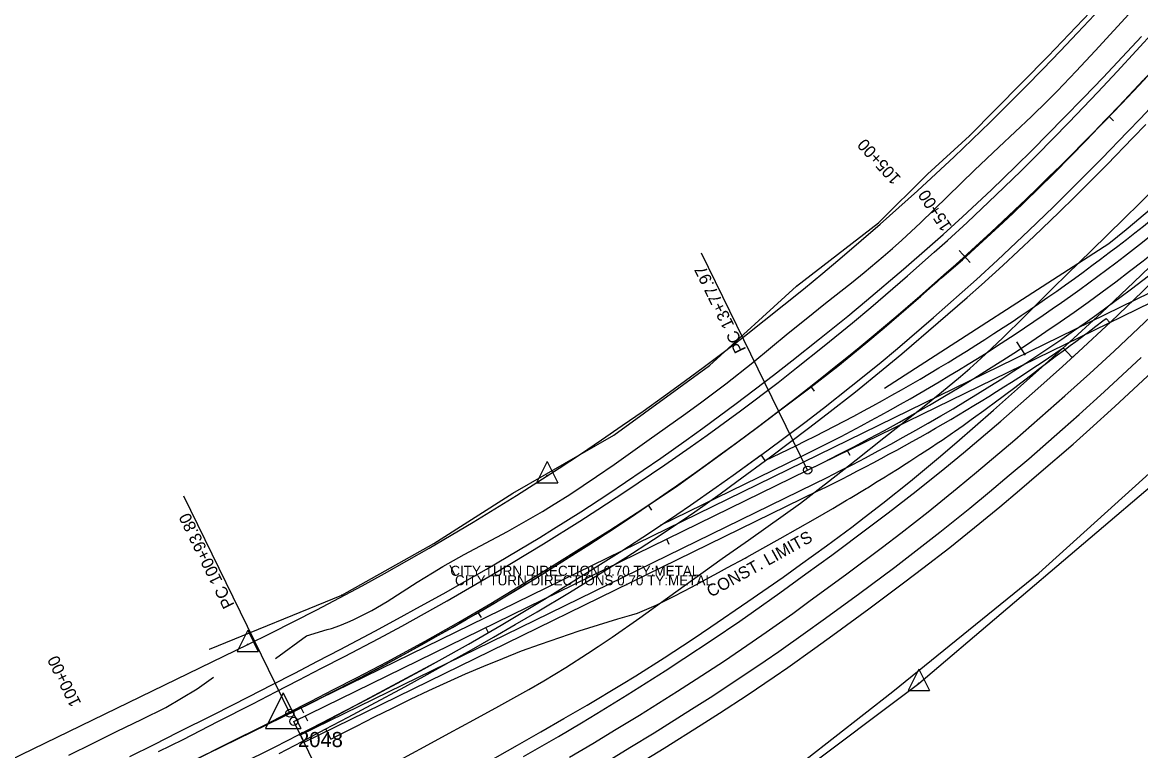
# Model space of a CAD drawing. Extents: x 1674300 to 1677920, y 225056 to 231852.
# Drawn here: x 1676432 to 1676987, y 227668 to 228030 of the extents above; entities that cross this region are included whole.
import ezdxf

# ---------------------------------------------------------------- set-up
doc = ezdxf.new("R2010")
doc.units = 0
for name, color, linetype in [('R_Annotation', 7, 'Continuous'), ('R_Horz Alg', 7, 'Continuous'), ('R_Horz Alg Annot', 7, 'Continuous'), ('R_Proposed Const Limits_Fill', 7, 'Continuous'), ('R_Proposed Road_Lane', 7, 'Continuous'), ('R_Proposed Road_Shoulder', 7, 'Continuous'), ('S_CAL_CORNER', 7, 'Continuous'), ('S_CAL_CORNER_ANNOT', 7, 'Continuous'), ('S_DITCHLINE', 7, 'Continuous'), ('S_EDGE_PAVEMENT', 7, 'Continuous'), ('S_EXIST_ROW', 7, 'Continuous'), ('S_EXISTING_ALIGNMENT', 7, 'Continuous'), ('S_FIBER_OPTIC_CABLE', 7, 'Continuous'), ('S_MSC_PT_SYM', 7, 'Continuous'), ('S_PAVEMENT_CROWN', 7, 'Continuous'), ('S_SHOULDER', 7, 'Continuous'), ('S_SIGN', 7, 'Continuous'), ('S_SIGN_ANNOT', 7, 'Continuous'), ('S_UTL_PT_SYM', 7, 'Continuous')]:
    doc.layers.add(name, color=color, linetype=linetype)

msp = doc.modelspace()

# ---------------------------------------------------------------- linework, layer by layer
at = {"layer": 'R_Horz Alg'}
for p, q in [((1676566.75, 227682.84), (1676822.03, 227807.69)), ((1676115.61, 227467.2), (1676564.78, 227686.88))]:
    msp.add_line(p, q, dxfattribs=at)
for centre, radius, end in [((1675928.16, 228988.54), 1449, 0.80558), ((1676402.48, 228665.51), 954.93, 328.88259)]:
    msp.add_arc(centre, radius, 296.0624, end, dxfattribs=at)
at = {"layer": 'R_Horz Alg Annot'}
for p, q in [((1676564.78, 227686.88), (1677389.93, 228090.45)), ((1676822.03, 227807.69), (1677074.66, 227931.25))]:
    msp.add_line(p, q, dxfattribs=at)
for points in [[(1676974.02, 227981.32), (1676971.86, 227983.41)], [(1676822.03, 227807.69), (1676769.3, 227915.48)], [(1676897.38, 227916.79), (1676902.74, 227910.86)], [(1676925.73, 227871.49), (1676930.13, 227864.81)], [(1676825.49, 227847.01), (1676823.64, 227849.36)], [(1676843.08, 227814.93), (1676841.7, 227817.59)], [(1676564.78, 227686.88), (1676512.05, 227794.68)], [(1676744.64, 227787.84), (1676742.95, 227790.32)], [(1676753.3, 227770.74), (1676751.99, 227773.43)], [(1676659.89, 227734.4), (1676658.38, 227736.99)], [(1676663.47, 227726.8), (1676662.15, 227729.5)], [(1676571.67, 227686.93), (1676570.34, 227689.61)], [(1676619.47, 227575.04), (1676566.75, 227682.84)], [(1676573.64, 227682.87), (1676572.32, 227685.56)]]:
    msp.add_lwpolyline(points, dxfattribs=at)
for centre in [(1676822.03, 227807.69), (1676564.78, 227686.88), (1676566.75, 227682.84)]:
    msp.add_circle(centre, 2, dxfattribs=at)
at = {"layer": 'R_Proposed Const Limits_Fill'}
for p, q in [((1676970.31, 227883.06), (1676972.23, 227881.05)), ((1676585.15, 227673.94), (1676582.55, 227679.05))]:
    msp.add_line(p, q, dxfattribs=at)
for points in [[(1676860.25, 227848.42), (1676971.76, 227920.24)], [(1676585.15, 227673.94), (1676588.94, 227675.93), (1676597.88, 227680.41), (1676606.76, 227685.02), (1676615.73, 227689.44), (1676624.67, 227693.92), (1676633.73, 227698.17), (1676642.85, 227702.29), (1676651.99, 227706.38), (1676661.2, 227710.33), (1676670.5, 227714.1), (1676679.82, 227717.84), (1676689.32, 227721.21), (1676698.84, 227724.53), (1676708.42, 227727.76), (1676718.1, 227730.78), (1676727.79, 227733.78), (1676734.61, 227735.81), (1676737.54, 227736.67), (1676746.79, 227740.54), (1676755.71, 227745.06), (1676764.59, 227749.65), (1676773.38, 227754.43), (1676777.77, 227756.83), (1676782.16, 227759.23), (1676790.94, 227764.02), (1676791.82, 227764.49), (1676799.7, 227768.86), (1676808.45, 227773.71), (1676817.16, 227778.65), (1676825.85, 227783.62), (1676834.5, 227788.69), (1676841.39, 227792.77), (1676843.11, 227793.8), (1676851.16, 227798.64), (1676851.72, 227798.97), (1676856.62, 227801.97), (1676860.5, 227804.37), (1676862.05, 227805.32), (1676867.46, 227808.7), (1676869.23, 227809.82), (1676872.83, 227812.15), (1676877.85, 227815.42), (1676878.17, 227815.64), (1676883.52, 227819.1), (1676886.46, 227821.03), (1676888.82, 227822.64), (1676894.08, 227826.23), (1676894.95, 227826.82), (1676899.3, 227829.88), (1676903.32, 227832.77), (1676904.47, 227833.6), (1676909.62, 227837.34), (1676911.62, 227838.8), (1676914.76, 227841.08), (1676919.83, 227844.91), (1676919.84, 227844.92), (1676924.9, 227848.75), (1676928.01, 227851.1), (1676929.95, 227852.58), (1676934.98, 227856.45), (1676936.12, 227857.33), (1676939.99, 227860.33), (1676944.26, 227863.49), (1676945.07, 227864.09), (1676950.14, 227867.87), (1676952.43, 227869.57), (1676955.21, 227871.64), (1676960.26, 227875.42), (1676960.59, 227875.66), (1676965.3, 227879.22), (1676968.69, 227881.82), (1676970.31, 227883.06)]]:
    msp.add_lwpolyline(points, dxfattribs=at)
msp.add_arc((1676364.65, 228668.23), 963.36, 309.06481, 319.55161, dxfattribs=at)
at = {"layer": 'R_Proposed Road_Lane'}
for p, q in [((1676748.93, 227780.28), (1676818.73, 227814.42)), ((1676570.05, 227676.1), (1676825.32, 227800.95)), ((1676570.05, 227676.1), (1676638.9, 227713))]:
    msp.add_line(p, q, dxfattribs=at)
for points in [[(1676953.5, 227863.64), (1676956.64, 227866.52), (1676972.6, 227881.4), (1676988.37, 227896.5), (1676996.17, 227904.12), (1677007.75, 227915.68), (1677022.13, 227930.45), (1677031.62, 227940.39), (1677041.04, 227950.41), (1677050.47, 227960.42), (1677064.47, 227975.57), (1677071.28, 227983.29), (1677077.87, 227991.2), (1677081.05, 227995.24), (1677086, 228001.89), (1677089.18, 228006.41), (1677095.28, 228015.66), (1677102.54, 228027.13)], [(1676602.96, 227693.74), (1676603.67, 227694.11), (1676620.43, 227702.92), (1676631.53, 227708.93), (1676638.9, 227713), (1676653.56, 227721.26), (1676669.8, 227730.7), (1676680.55, 227737.1), (1676691.25, 227743.62), (1676701.94, 227750.13), (1676720.46, 227761.74), (1676729.67, 227767.63), (1676743.4, 227776.59), (1676757.03, 227785.7), (1676763.8, 227790.32), (1676776.54, 227799.18), (1676784.98, 227805.17), (1676798.91, 227815.26)]]:
    msp.add_lwpolyline(points, dxfattribs=at)
for radius, end in [(947.43, 317.63818), (962.43, 309.63823)]:
    msp.add_arc((1676402.48, 228665.51), radius, 296.0624, end, dxfattribs=at)
at = {"layer": 'R_Proposed Road_Shoulder'}
for p, q in [((1676949.06, 227868.5), (1676953.5, 227863.64)), ((1676800.97, 227812.42), (1676798.91, 227815.26)), ((1676800.97, 227812.42), (1676816.09, 227819.81)), ((1676571.81, 227672.51), (1676827.08, 227797.35)), ((1676571.81, 227672.51), (1676569.81, 227676.59))]:
    msp.add_line(p, q, dxfattribs=at)
for radius, end in [(941.43, 317.05629), (966.43, 304.44158)]:
    msp.add_arc((1676402.48, 228665.51), radius, 296.0624, end, dxfattribs=at)
at = {"layer": 'S_CAL_CORNER'}
for p, q in [((1676561.42, 227697.02), (1676552.61, 227679.29)), ((1676561.42, 227697.02), (1676552.61, 227679.29)), ((1676561.42, 227697.02), (1676552.61, 227679.29)), ((1676561.42, 227697.02), (1676552.61, 227679.29)), ((1676561.42, 227697.02), (1676570.14, 227679.29)), ((1676561.42, 227697.02), (1676570.14, 227679.29)), ((1676561.42, 227697.02), (1676570.14, 227679.29)), ((1676561.42, 227697.02), (1676570.14, 227679.29)), ((1676552.61, 227679.29), (1676570.14, 227679.29)), ((1676552.61, 227679.29), (1676570.14, 227679.29)), ((1676552.61, 227679.29), (1676570.14, 227679.29)), ((1676552.61, 227679.29), (1676570.14, 227679.29))]:
    msp.add_line(p, q, dxfattribs=at)
at = {"layer": 'S_DITCHLINE'}
for points in [[(1676557.64, 227714.12), (1676573.09, 227725.4), (1676583.33, 227728.42), (1676585.43, 227729.06), (1676589.57, 227730.51), (1676593.62, 227732.15), (1676596.28, 227733.34), (1676601.53, 227735.92), (1676605.4, 227738), (1676613.02, 227742.46), (1676628.03, 227751.95), (1676635.56, 227756.66), (1676640.82, 227759.78), (1676651.43, 227765.74), (1676672.81, 227777.22), (1676683.4, 227783.11), (1676690.27, 227787.16), (1676694.8, 227789.93), (1676703.79, 227795.62), (1676717.1, 227804.49), (1676725.88, 227810.55), (1676743.33, 227822.85), (1676760.37, 227834.97), (1676768.81, 227841.12), (1676781.31, 227850.55), (1676794.72, 227861.22), (1676812.4, 227875.73), (1676821.28, 227882.95), (1676830.91, 227890.62), (1676843.77, 227900.81), (1676850.15, 227905.95), (1676859.6, 227913.82), (1676864.24, 227917.84), (1676868.89, 227922.01), (1676878.02, 227930.53), (1676891.46, 227943.62), (1676904.91, 227956.71), (1676917.04, 227968.18), (1676933.22, 227983.46), (1676941.18, 227991.22), (1676946.01, 227996.08), (1676955.51, 228005.96), (1676964.85, 228016), (1676974.11, 228026.12), (1676983.36, 228036.25)], [(1676619.21, 227663.52), (1676631.55, 227670.24), (1676643.88, 227676.95), (1676656.22, 227683.66), (1676668.56, 227690.37), (1676683.49, 227698.72), (1676690.87, 227703.03), (1676701.83, 227709.66), (1676712.65, 227716.51), (1676718, 227720.02), (1676724.96, 227724.71), (1676738.72, 227734.32), (1676752.33, 227744.15), (1676765.94, 227753.99), (1676779.59, 227763.79), (1676792.57, 227772.92), (1676809.85, 227785.11), (1676818.4, 227791.33), (1676832.36, 227801.97), (1676846.14, 227812.86), (1676859.92, 227823.76), (1676879.09, 227838.84), (1676888.6, 227846.47), (1676897.95, 227854.27), (1676902.55, 227858.26), (1676908.13, 227863.25), (1676919.05, 227873.5), (1676929.77, 227883.98), (1676943.92, 227898.11), (1676951.02, 227905.16), (1676963.08, 227916.92), (1676979.21, 227932.56), (1676987.2, 227940.45), (1677000.17, 227953.65)], [(1676454.95, 227666.05), (1676466.98, 227671.97), (1676479.02, 227677.89), (1676491.05, 227683.81), (1676503.09, 227689.73), (1676518.65, 227699.02), (1676526.82, 227704.87)]]:
    msp.add_lwpolyline(points, dxfattribs=at)
at = {"layer": 'S_EDGE_PAVEMENT'}
for points in [[(1676499.45, 227667.86), (1676511.68, 227673.86), (1676528.99, 227682.71), (1676546.31, 227691.55), (1676557.7, 227697.44), (1676569.08, 227703.32), (1676580.47, 227709.21), (1676591.86, 227715.09), (1676608.97, 227724.09), (1676620.31, 227730.21), (1676631.57, 227736.48), (1676642.83, 227742.74), (1676664.28, 227755.12), (1676674.93, 227761.44), (1676690.82, 227771.09), (1676708.87, 227782.39), (1676717.84, 227788.15), (1676731.2, 227796.91), (1676751.05, 227810.35), (1676763.67, 227819.17), (1676772.03, 227825.14), (1676788.62, 227837.24), (1676807.31, 227851.32), (1676816.56, 227858.49), (1676830.31, 227869.4), (1676844.24, 227880.82), (1676853.44, 227888.54), (1676871.63, 227904.22), (1676884.89, 227915.95), (1676891.46, 227921.87), (1676901.25, 227930.84), (1676915.74, 227944.48), (1676927.9, 227956.29), (1676935.92, 227964.26), (1676951.76, 227980.38), (1676966.27, 227995.53), (1676975.83, 228005.73), (1676985.29, 228016.04), (1676994.74, 228026.34)], [(1676539.8, 227661.38), (1676557.45, 227670.2), (1676569.01, 227676.18), (1676580.56, 227682.15), (1676592.12, 227688.13), (1676603.67, 227694.11), (1676620.43, 227702.92), (1676631.53, 227708.93), (1676638.9, 227713), (1676653.56, 227721.26), (1676669.8, 227730.7), (1676680.55, 227737.1), (1676691.25, 227743.62), (1676701.94, 227750.13), (1676720.46, 227761.74), (1676729.67, 227767.63), (1676743.4, 227776.59), (1676757.03, 227785.7), (1676763.8, 227790.32), (1676776.54, 227799.18), (1676784.98, 227805.17), (1676801.74, 227817.32), (1676820.56, 227831.36), (1676829.88, 227838.49), (1676843.73, 227849.37), (1676857.53, 227860.58), (1676866.63, 227868.17), (1676884.63, 227883.6), (1676898.83, 227896.15), (1676905.87, 227902.49), (1676916.35, 227912.09), (1676931.88, 227926.7), (1676944.11, 227938.52), (1676952.18, 227946.48), (1676968.16, 227962.57), (1676980.99, 227975.79), (1676987.34, 227982.45), (1676996.8, 227992.52)], [(1676680.84, 227665.29), (1676698.16, 227675.29), (1676709.63, 227682.09), (1676717.25, 227686.68), (1676732.39, 227696.01), (1676751.22, 227707.95), (1676760.57, 227714.03), (1676774.51, 227723.28), (1676788.32, 227732.7), (1676795.19, 227737.48), (1676808.2, 227746.7), (1676821.09, 227756.09), (1676833.98, 227765.47), (1676852.77, 227779.44), (1676862.1, 227786.51), (1676875.97, 227797.27), (1676890.15, 227808.64), (1676899.5, 227816.34), (1676917.98, 227832.01), (1676936.44, 227848.2), (1676948.6, 227859.15), (1676956.64, 227866.52), (1676972.6, 227881.4), (1676988.37, 227896.5)], [(1676721.65, 227662.42), (1676733.68, 227669.77), (1676745.7, 227677.12), (1676764.28, 227688.81), (1676773.52, 227694.75), (1676787.29, 227703.77), (1676800.96, 227712.96), (1676807.74, 227717.62), (1676821.02, 227726.94), (1676829.81, 227733.24), (1676847.27, 227746), (1676865.35, 227759.54), (1676874.33, 227766.39), (1676887.68, 227776.81), (1676902.58, 227788.79), (1676912.41, 227796.9), (1676922.15, 227805.14), (1676931.88, 227813.37), (1676948.66, 227827.99), (1676956.98, 227835.38), (1676969.35, 227846.58), (1676978.52, 227855.1), (1676987.68, 227863.63)]]:
    msp.add_lwpolyline(points, dxfattribs=at)
at = {"layer": 'S_EXIST_ROW'}
for p, q in [((1676877.29, 227701.73), (1677045.25, 227844.61)), ((1676692.64, 227812.02), (1676687.35, 227801.39)), ((1676692.64, 227812.02), (1676697.88, 227801.39)), ((1676692.62, 227804.93), (1676692.62, 227804.93)), ((1676687.35, 227801.39), (1676697.88, 227801.39)), ((1676543.81, 227728.11), (1676538.52, 227717.47)), ((1676543.81, 227728.11), (1676549.04, 227717.47)), ((1676060.31, 227485.79), (1676543.79, 227721.01)), ((1676543.79, 227721.01), (1676543.79, 227721.01)), ((1676538.52, 227717.47), (1676549.04, 227717.47)), ((1676877.31, 227708.82), (1676872.02, 227698.19)), ((1676877.31, 227708.82), (1676882.54, 227698.19)), ((1676744.37, 227601.87), (1676877.29, 227701.73)), ((1676872.02, 227698.19), (1676882.54, 227698.19)), ((1676877.29, 227701.73), (1676877.29, 227701.73))]:
    msp.add_line(p, q, dxfattribs=at)
for centre, radius in [((1676692.62, 227804.93), 0.18), ((1676692.62, 227804.93), 0.09), ((1676543.79, 227721.01), 0.18), ((1676543.79, 227721.01), 0.09), ((1676877.29, 227701.73), 0.18), ((1676877.29, 227701.73), 0.09)]:
    msp.add_circle(centre, radius, dxfattribs=at)
msp.add_arc((1675926.71, 228989.39), 1410.53, 295.94359, 0.85682, dxfattribs=at)
at = {"layer": 'S_EXISTING_ALIGNMENT'}
msp.add_line((1676112.44, 227466.67), (1676561.29, 227685.05), dxfattribs=at)
for start, end in [(315.98862, 345.81316), (295.94359, 315.98862)]:
    msp.add_arc((1675926.71, 228989.39), 1450.53, start, end, dxfattribs=at)
at = {"layer": 'S_FIBER_OPTIC_CABLE'}
for p, q in [((1676941.57, 228013.45), (1676983.24, 228057.34)), ((1676902.41, 227973.8), (1676941.57, 228013.45)), ((1676881.55, 227954.79), (1676902.41, 227973.8)), ((1676857.28, 227930.62), (1676881.55, 227954.79)), ((1676816.44, 227899.08), (1676857.28, 227930.62)), ((1676773.26, 227859.62), (1676816.44, 227899.08)), ((1676725.71, 227825.01), (1676773.26, 227859.62)), ((1676675.62, 227796.16), (1676725.71, 227825.01)), ((1676936.92, 227756.51), (1676993.59, 227807.69)), ((1676636.29, 227771.17), (1676675.62, 227796.16)), ((1676590.51, 227745.62), (1676636.29, 227771.17)), ((1676864.37, 227697.61), (1676936.92, 227756.51)), ((1676524.86, 227718.7), (1676590.51, 227745.62)), ((1676821.12, 227663.91), (1676864.37, 227697.61))]:
    msp.add_line(p, q, dxfattribs=at)
at = {"layer": 'S_MSC_PT_SYM'}
for points in [[(1676644.47, 227760.17), (1676644.47, 227760.22), (1676644.47, 227760.17), (1676644.42, 227760.17), (1676644.47, 227760.17), (1676644.47, 227760.12), (1676644.47, 227760.17), (1676644.52, 227760.17)], [(1676646.79, 227755.44), (1676646.79, 227755.49), (1676646.79, 227755.44), (1676646.74, 227755.44), (1676646.79, 227755.44), (1676646.79, 227755.39), (1676646.79, 227755.44), (1676646.84, 227755.44)]]:
    msp.add_lwpolyline(points, dxfattribs=at)
at = {"layer": 'S_PAVEMENT_CROWN'}
for points in [[(1676516.69, 227663.29), (1676534.44, 227672.12), (1676552.19, 227680.94), (1676563.62, 227686.84), (1676575.04, 227692.73), (1676586.46, 227698.63), (1676597.89, 227704.52), (1676613.1, 227712.47), (1676620.67, 227716.52), (1676631.97, 227722.67), (1676648.78, 227732.15), (1676664.65, 227741.49), (1676675.16, 227747.83), (1676696.09, 227760.67), (1676709.88, 227769.24), (1676723.67, 227777.8), (1676737.33, 227786.55), (1676750.85, 227795.53), (1676757.53, 227800.12), (1676770.18, 227809.13), (1676778.53, 227815.24), (1676795.14, 227827.6), (1676813.86, 227841.57), (1676823.17, 227848.63), (1676836.98, 227859.39), (1676850.91, 227870.74), (1676860.08, 227878.46), (1676878.25, 227894.1), (1676888.59, 227903.18), (1676898.92, 227912.26), (1676909.14, 227921.46), (1676919.24, 227930.77), (1676924.24, 227935.49), (1676936.46, 227947.31), (1676944.49, 227955.3), (1676960.36, 227971.5), (1676969.86, 227981.46), (1676979.36, 227991.43), (1676988.75, 228001.5)], [(1676703.71, 227665), (1676715.33, 227671.91), (1676726.88, 227678.95), (1676738.42, 227685.98), (1676757.29, 227697.82), (1676766.67, 227703.83), (1676780.65, 227712.98), (1676794.49, 227722.33), (1676801.36, 227727.08), (1676814.6, 227736.48), (1676823.36, 227742.84), (1676840.79, 227755.69), (1676859.15, 227769.42), (1676868.28, 227776.36), (1676881.84, 227786.93), (1676896.36, 227798.66), (1676905.93, 227806.61), (1676924.9, 227822.74), (1676941.58, 227837.25), (1676949.86, 227844.57), (1676962.19, 227855.65), (1676974.4, 227866.87), (1676980.44, 227872.54), (1676992.37, 227883.95)]]:
    msp.add_lwpolyline(points, dxfattribs=at)
at = {"layer": 'S_SHOULDER'}
for points in [[(1676485.19, 227665.35), (1676497.26, 227671.4), (1676509.33, 227677.46), (1676526.95, 227686.28), (1676544.58, 227695.11), (1676555.87, 227700.98), (1676567.16, 227706.86), (1676578.45, 227712.73), (1676589.74, 227718.6), (1676606.9, 227727.65), (1676618.29, 227733.77), (1676629.61, 227740.01), (1676640.94, 227746.25), (1676662.45, 227758.48), (1676673.13, 227764.72), (1676689.03, 227774.29), (1676695.82, 227778.48), (1676709.31, 227787.01), (1676722.68, 227795.72), (1676731.53, 227801.63), (1676749.06, 227813.67), (1676761.63, 227822.56), (1676769.95, 227828.57), (1676786.46, 227840.75), (1676805.03, 227854.85), (1676814.23, 227862), (1676827.93, 227872.86), (1676841.95, 227884.27), (1676851.23, 227891.96), (1676869.6, 227907.56), (1676882.78, 227919.03), (1676889.32, 227924.83), (1676899.05, 227933.62), (1676913.43, 227947.02), (1676925.55, 227958.78), (1676933.54, 227966.71), (1676949.36, 227982.73), (1676959.07, 227992.77), (1676968.79, 228002.8), (1676978.38, 228012.96), (1676987.84, 228023.23)], [(1676559.43, 227666.82), (1676570.84, 227672.86), (1676582.26, 227678.89), (1676593.67, 227684.93), (1676605.09, 227690.97), (1676621.82, 227699.95), (1676632.91, 227706.04), (1676643.95, 227712.24), (1676654.99, 227718.43), (1676665.88, 227724.68), (1676676.77, 227730.93), (1676687.6, 227737.28), (1676703.77, 227746.93), (1676722.45, 227758.42), (1676731.71, 227764.27), (1676745.51, 227773.22), (1676759.16, 227782.38), (1676765.93, 227787.04), (1676778.55, 227795.98), (1676786.9, 227802.03), (1676803.5, 227814.28), (1676822.41, 227828.48), (1676831.8, 227835.67), (1676845.75, 227846.62), (1676859.62, 227857.9), (1676868.77, 227865.53), (1676886.9, 227881.02), (1676901.24, 227893.54), (1676908.36, 227899.86), (1676918.96, 227909.41), (1676934.66, 227923.98), (1676946.86, 227935.69), (1676954.9, 227943.6), (1676970.81, 227959.61), (1676983.65, 227972.85), (1676990.02, 227979.53)], [(1676656.84, 227659.05), (1676677.87, 227671.01), (1676689.41, 227677.6), (1676700.95, 227684.2), (1676712.44, 227690.88), (1676729.54, 227701.1), (1676736.64, 227705.48), (1676750.74, 227714.42), (1676764.71, 227723.57), (1676773.96, 227729.76), (1676792.33, 227742.34), (1676809.79, 227754.55), (1676818.46, 227760.73), (1676831.39, 227770.12), (1676843.92, 227779.42), (1676850.14, 227784.14), (1676859.4, 227791.3), (1676873.12, 227802.25), (1676887.01, 227813.8), (1676896.16, 227821.63), (1676914.3, 227837.49), (1676926.31, 227848.15), (1676938.32, 227858.82), (1676950.25, 227869.58), (1676967.99, 227885.88), (1676984.05, 227901.03), (1676992, 227908.68)], [(1676738.73, 227662.21), (1676750.7, 227669.55), (1676769.11, 227681.11), (1676778.26, 227686.98), (1676791.9, 227695.91), (1676805.42, 227705.02), (1676812.13, 227709.66), (1676825.64, 227719.24), (1676834.58, 227725.72), (1676852.37, 227738.82), (1676870.37, 227752.23), (1676879.32, 227759.01), (1676892.63, 227769.3), (1676907.6, 227781.29), (1676917.46, 227789.41), (1676927.22, 227797.68), (1676936.97, 227805.94), (1676953.88, 227820.66), (1676962.26, 227828.1), (1676974.74, 227839.37), (1676983.99, 227847.94), (1676993.24, 227856.51)]]:
    msp.add_lwpolyline(points, dxfattribs=at)
at = {"layer": 'S_SIGN'}
msp.add_line((1676644.47, 227760.17), (1676646.79, 227755.44), dxfattribs=at)
at = {"layer": 'S_UTL_PT_SYM'}
for points in [[(1676941.57, 228013.45), (1676941.57, 228013.5), (1676941.57, 228013.45), (1676941.53, 228013.45), (1676941.57, 228013.45), (1676941.57, 228013.4), (1676941.57, 228013.45), (1676941.62, 228013.45)], [(1676902.41, 227973.8), (1676902.41, 227973.85), (1676902.41, 227973.8), (1676902.36, 227973.8), (1676902.41, 227973.8), (1676902.41, 227973.75), (1676902.41, 227973.8), (1676902.46, 227973.8)], [(1676881.55, 227954.79), (1676881.55, 227954.84), (1676881.55, 227954.79), (1676881.5, 227954.79), (1676881.55, 227954.79), (1676881.55, 227954.74), (1676881.55, 227954.79), (1676881.6, 227954.79)], [(1676857.28, 227930.62), (1676857.28, 227930.67), (1676857.28, 227930.62), (1676857.23, 227930.62), (1676857.28, 227930.62), (1676857.28, 227930.57), (1676857.28, 227930.62), (1676857.33, 227930.62)], [(1676816.44, 227899.08), (1676816.44, 227899.13), (1676816.44, 227899.08), (1676816.39, 227899.08), (1676816.44, 227899.08), (1676816.44, 227899.03), (1676816.44, 227899.08), (1676816.49, 227899.08)], [(1676773.26, 227859.62), (1676773.26, 227859.67), (1676773.26, 227859.62), (1676773.21, 227859.62), (1676773.26, 227859.62), (1676773.26, 227859.57), (1676773.26, 227859.62), (1676773.31, 227859.62)], [(1676725.71, 227825.01), (1676725.71, 227825.06), (1676725.71, 227825.01), (1676725.66, 227825.01), (1676725.71, 227825.01), (1676725.71, 227824.96), (1676725.71, 227825.01), (1676725.76, 227825.01)], [(1676675.62, 227796.16), (1676675.62, 227796.21), (1676675.62, 227796.16), (1676675.57, 227796.16), (1676675.62, 227796.16), (1676675.62, 227796.11), (1676675.62, 227796.16), (1676675.67, 227796.16)], [(1676636.29, 227771.17), (1676636.29, 227771.22), (1676636.29, 227771.17), (1676636.24, 227771.17), (1676636.29, 227771.17), (1676636.29, 227771.12), (1676636.29, 227771.17), (1676636.34, 227771.17)], [(1676936.92, 227756.51), (1676936.92, 227756.56), (1676936.92, 227756.51), (1676936.87, 227756.51), (1676936.92, 227756.51), (1676936.92, 227756.46), (1676936.92, 227756.51), (1676936.97, 227756.51)], [(1676590.51, 227745.62), (1676590.51, 227745.67), (1676590.51, 227745.62), (1676590.46, 227745.62), (1676590.51, 227745.62), (1676590.51, 227745.57), (1676590.51, 227745.62), (1676590.56, 227745.62)], [(1676524.86, 227718.7), (1676524.86, 227718.75), (1676524.86, 227718.7), (1676524.81, 227718.7), (1676524.86, 227718.7), (1676524.86, 227718.65), (1676524.86, 227718.7), (1676524.91, 227718.7)], [(1676864.37, 227697.61), (1676864.37, 227697.66), (1676864.37, 227697.61), (1676864.32, 227697.61), (1676864.37, 227697.61), (1676864.37, 227697.56), (1676864.37, 227697.61), (1676864.42, 227697.61)]]:
    msp.add_lwpolyline(points, dxfattribs=at)

# ---------------------------------------------------------------- texts
at = {"layer": 'R_Annotation'}
msp.add_text('CONST. LIMITS', height=6, rotation=28.9977, dxfattribs=at).set_placement((1676773.93, 227744.29))
at = {"layer": 'R_Horz Alg Annot'}
for s, rotation, p in [('105+00', 132.1242, (1676868.75, 227952.92)), ('15+00', 123.3843, (1676893.94, 227928.89)), ('PC 13+77.97', 116.0624, (1676791.57, 227867.68)), ('PC 100+93.80', 116.0624, (1676537.33, 227740.72)), ('100+00', 116.0624, (1676461.24, 227691.9))]:
    msp.add_text(s, height=6, rotation=rotation, dxfattribs=at).set_placement(p)
at = {"layer": 'S_CAL_CORNER_ANNOT'}
msp.add_text('2048', height=7.5, dxfattribs=at).set_placement((1676568.79, 227670.05))
msp.add_text('2048', height=7.5, dxfattribs=at).set_placement((1676568.79, 227670.05))
msp.add_text('2048', height=7.5, dxfattribs=at).set_placement((1676568.79, 227670.05))
msp.add_text('2048', height=7.5, dxfattribs=at).set_placement((1676568.79, 227670.05))
at = {"layer": 'S_SIGN_ANNOT'}
for s, p in [('CITY TURN DIRECTION 0.70 TY:METAL', (1676644.47, 227755.17)), ('CITY TURN DIRECTIONS 0.70 TY:METAL', (1676646.79, 227750.44))]:
    msp.add_text(s, height=5, dxfattribs=at).set_placement(p)

doc.saveas('drawing.dxf')
